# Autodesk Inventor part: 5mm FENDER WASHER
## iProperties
Created: 2007-03
Part Number: 5mm FENDER WASHER
Material: Steel
Document SubType Name: Modeling
Designer: Andy Moles
Mass: 2.50314 g
Surface Area: 6.40885 cm^2
Volume: 0.318872 cm^3
Density: 7.85 g/cm^3
Author: Andy Moles
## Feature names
1. Extrusion1
